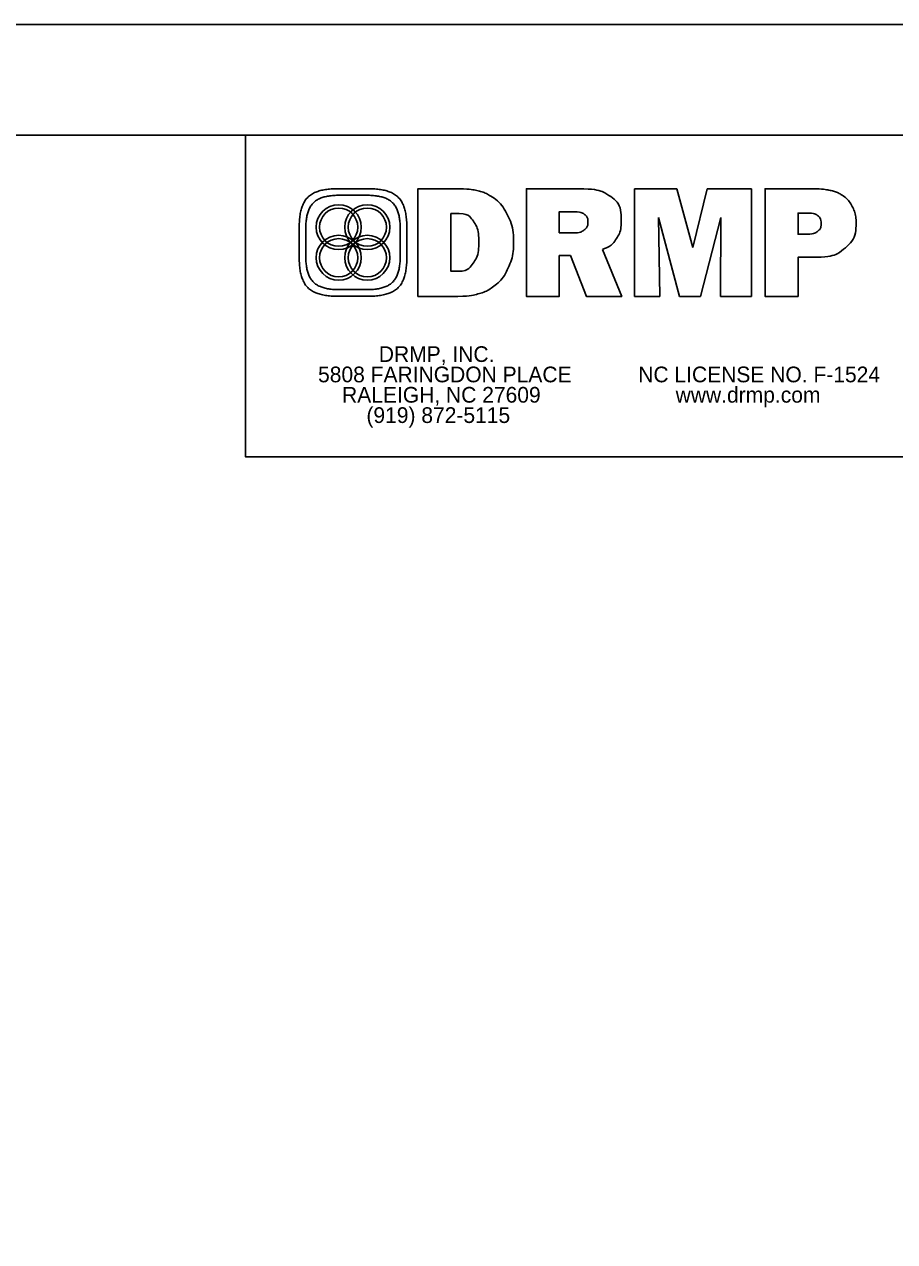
# Model space of a CAD drawing. Extents: x 573078 to 573143.6, y -55221.3 to -55199.3.
# Drawn here: x 573103.51 to 573107.44, y -55204.8 to -55199.3 of the extents above; entities that cross this region are included whole.
import ezdxf

# ---------------------------------------------------------------- set-up
doc = ezdxf.new("R2010")
doc.units = 0
for name, color, linetype in [('Pattern 1', 7, 'Continuous'), ('Pattern 2', 7, 'Continuous'), ('Sheet Plan CELL', 7, 'Continuous'), ('Sheet Plot Border Inside CELL', 7, 'Continuous')]:
    doc.layers.add(name, color=color, linetype=linetype)

msp = doc.modelspace()

# ---------------------------------------------------------------- linework, layer by layer
at = {"layer": 'Pattern 1'}
for p, q in [((573104.9279, -55200.041), (573105.0688, -55200.041)), ((573105.0602, -55200.0707), (573104.9365, -55200.0707)), ((573106.2698, -55200.5276), (573106.2698, -55200.0415)), ((573106.2698, -55200.0415), (573106.461, -55200.0415)), ((573106.461, -55200.0415), (573106.5338, -55200.3069)), ((573106.5338, -55200.3069), (573106.598, -55200.0415)), ((573106.598, -55200.0415), (573106.7977, -55200.0415)), ((573106.7977, -55200.0415), (573106.7977, -55200.5276)), ((573106.473, -55200.5276), (573106.3783, -55200.1711)), ((573106.3783, -55200.1711), (573106.3835, -55200.5276)), ((573106.6599, -55200.1711), (573106.5673, -55200.5276)), ((573106.6575, -55200.5276), (573106.6599, -55200.1711)), ((573104.7555, -55200.3543), (573104.7555, -55200.2134)), ((573104.7852, -55200.222), (573104.7852, -55200.3457)), ((573105.2115, -55200.3457), (573105.2115, -55200.222)), ((573105.2413, -55200.2134), (573105.2413, -55200.3543)), ((573105.0688, -55200.5268), (573104.9279, -55200.5268)), ((573104.9365, -55200.497), (573105.0602, -55200.497)), ((573106.3835, -55200.5276), (573106.2698, -55200.5276)), ((573106.5673, -55200.5276), (573106.473, -55200.5276)), ((573106.7977, -55200.5276), (573106.6575, -55200.5276))]:
    msp.add_line(p, q, dxfattribs=at)
for points in [[(573105.4719, -55200.5276), (573105.2914, -55200.5276), (573105.2914, -55200.0415), (573105.4784, -55200.0415)], [(573106.1248, -55200.3152), (573106.2124, -55200.5276), (573106.0527, -55200.5276), (573105.9805, -55200.3432), (573105.9296, -55200.3432), (573105.9296, -55200.5276), (573105.7817, -55200.5276), (573105.7817, -55200.0415), (573106.0192, -55200.0415)], [(573107.0949, -55200.3504), (573107.0086, -55200.3504), (573107.0086, -55200.5276), (573106.8596, -55200.5276), (573106.8596, -55200.0415), (573107.0668, -55200.0415)], [(573105.4784, -55200.1532), (573105.4404, -55200.1532), (573105.4404, -55200.4139), (573105.4739, -55200.4139)], [(573105.9983, -55200.1452), (573105.9296, -55200.1452), (573105.9296, -55200.2402), (573106.0004, -55200.2402)], [(573107.0576, -55200.1513), (573107.0086, -55200.1513), (573107.0086, -55200.2467), (573107.0487, -55200.2467)]]:
    msp.add_lwpolyline(points, dxfattribs=at)
for points, degree in [([(573104.7555, -55200.2134), (573104.7555, -55200.1186), (573104.8331, -55200.041), (573104.9279, -55200.041)], 2), ([(573104.9365, -55200.0707), (573104.8533, -55200.0707), (573104.7852, -55200.1388), (573104.7852, -55200.222)], 2), ([(573105.2115, -55200.222), (573105.2115, -55200.1388), (573105.1434, -55200.0707), (573105.0602, -55200.0707)], 2), ([(573105.0688, -55200.041), (573105.1636, -55200.041), (573105.2413, -55200.1186), (573105.2413, -55200.2134)], 2), ([(573105.4784, -55200.0415), (573105.5078, -55200.0415), (573105.5342, -55200.0441), (573105.5575, -55200.0493), (573105.5808, -55200.0546), (573105.6011, -55200.0627), (573105.6184, -55200.0736), (573105.6517, -55200.0946), (573105.6776, -55200.1235), (573105.6959, -55200.1603), (573105.7143, -55200.1972), (573105.7235, -55200.2385), (573105.7235, -55200.2843), (573105.7235, -55200.3249), (573105.7154, -55200.3629), (573105.6992, -55200.3983), (573105.683, -55200.4336), (573105.661, -55200.4618), (573105.6331, -55200.4827), (573105.6124, -55200.498), (573105.5889, -55200.5093), (573105.5628, -55200.5166), (573105.5366, -55200.5239), (573105.5064, -55200.5276), (573105.4719, -55200.5276)], 3), ([(573106.0192, -55200.0415), (573106.0828, -55200.0415), (573106.1304, -55200.0533), (573106.1621, -55200.0769), (573106.1938, -55200.1005), (573106.2097, -55200.136), (573106.2097, -55200.1834), (573106.2097, -55200.2163), (573106.2024, -55200.244), (573106.1879, -55200.2666), (573106.1735, -55200.2892), (573106.1524, -55200.3054), (573106.1248, -55200.3152)], 3), ([(573107.0668, -55200.0415), (573107.0992, -55200.0415), (573107.1261, -55200.0435), (573107.1474, -55200.0474), (573107.1688, -55200.0514), (573107.1865, -55200.0578), (573107.2006, -55200.0664), (573107.2235, -55200.0808), (573107.2407, -55200.0989), (573107.2525, -55200.1208), (573107.2642, -55200.1427), (573107.2701, -55200.1676), (573107.2701, -55200.1954), (573107.2701, -55200.2417), (573107.254, -55200.2792), (573107.2219, -55200.3077), (573107.1897, -55200.3362), (573107.1474, -55200.3504), (573107.0949, -55200.3504)], 3), ([(573105.4739, -55200.4139), (573105.5018, -55200.4139), (573105.5242, -55200.4019), (573105.541, -55200.378), (573105.5578, -55200.354), (573105.5662, -55200.3221), (573105.5662, -55200.2822), (573105.5662, -55200.2427), (573105.5582, -55200.2114), (573105.5423, -55200.1881), (573105.5265, -55200.1648), (573105.5051, -55200.1532), (573105.4784, -55200.1532)], 3), ([(573106.0004, -55200.2402), (573106.0177, -55200.2402), (573106.0318, -55200.2358), (573106.0428, -55200.2269), (573106.0537, -55200.218), (573106.0592, -55200.2066), (573106.0592, -55200.1927), (573106.0592, -55200.1768), (573106.0541, -55200.1649), (573106.0439, -55200.157), (573106.0338, -55200.1491), (573106.0186, -55200.1452), (573105.9983, -55200.1452)], 3), ([(573107.0487, -55200.2467), (573107.0688, -55200.2467), (573107.0844, -55200.2425), (573107.0956, -55200.234), (573107.1068, -55200.2256), (573107.1124, -55200.2139), (573107.1124, -55200.1988), (573107.1124, -55200.1836), (573107.1077, -55200.1718), (573107.0983, -55200.1636), (573107.089, -55200.1554), (573107.0754, -55200.1513), (573107.0576, -55200.1513)], 3), ([(573104.9279, -55200.5268), (573104.8331, -55200.5268), (573104.7555, -55200.4491), (573104.7555, -55200.3543)], 2), ([(573104.7852, -55200.3457), (573104.7852, -55200.4289), (573104.8533, -55200.497), (573104.9365, -55200.497)], 2), ([(573105.0602, -55200.497), (573105.1434, -55200.497), (573105.2115, -55200.4289), (573105.2115, -55200.3457)], 2), ([(573105.2413, -55200.3543), (573105.2413, -55200.4491), (573105.1636, -55200.5268), (573105.0688, -55200.5268)], 2)]:
    msp.add_open_spline(points, degree=degree, dxfattribs=at)
at = {"layer": 'Pattern 2'}
for centre, radius in [((573104.9337, -55200.2148), 0.1016), ((573104.9337, -55200.2148), 0.0864), ((573105.063, -55200.2148), 0.1016), ((573105.063, -55200.2148), 0.0864), ((573104.9337, -55200.3529), 0.1016), ((573105.063, -55200.3529), 0.1016), ((573104.9337, -55200.3529), 0.0864), ((573105.063, -55200.3529), 0.0864)]:
    msp.add_circle(centre, radius, dxfattribs=at)
at = {"layer": 'Sheet Plan CELL'}
for points in [[(573081.5142, -55199.7984), (573111.5142, -55199.7984), (573111.5142, -55220.7984), (573081.5142, -55220.7984)], [(573107.5132, -55201.252), (573104.5124, -55201.252), (573104.5124, -55199.7984), (573107.5132, -55199.7984)]]:
    msp.add_lwpolyline(points, close=True, dxfattribs=at)
at = {"layer": 'Sheet Plot Border Inside CELL'}
msp.add_lwpolyline([(573112.0142, -55199.2984), (573078.0142, -55199.2984), (573078.0142, -55221.2984), (573112.0142, -55221.2984)], close=True, dxfattribs=at)

# ---------------------------------------------------------------- texts
at = {"layer": 'Pattern 2'}
for s, height, p in [('DRMP, INC.', 0.07099, (573105.1149, -55200.8238)), ('5808 FARINGDON PLACE', 0.070991, (573104.8406, -55200.9157)), ('NC LICENSE NO. F-1524', 0.070991, (573106.2865, -55200.9157)), ('RALEIGH, NC 27609', 0.070991, (573104.9489, -55201.0076)), ('www.drmp.com', 0.070991, (573106.4554, -55201.0076)), ('(919) 872-5115', 0.070991, (573105.059, -55201.0995))]:
    msp.add_text(s, height=height, rotation=360, dxfattribs=at).set_placement(p)

doc.saveas('drawing.dxf')
